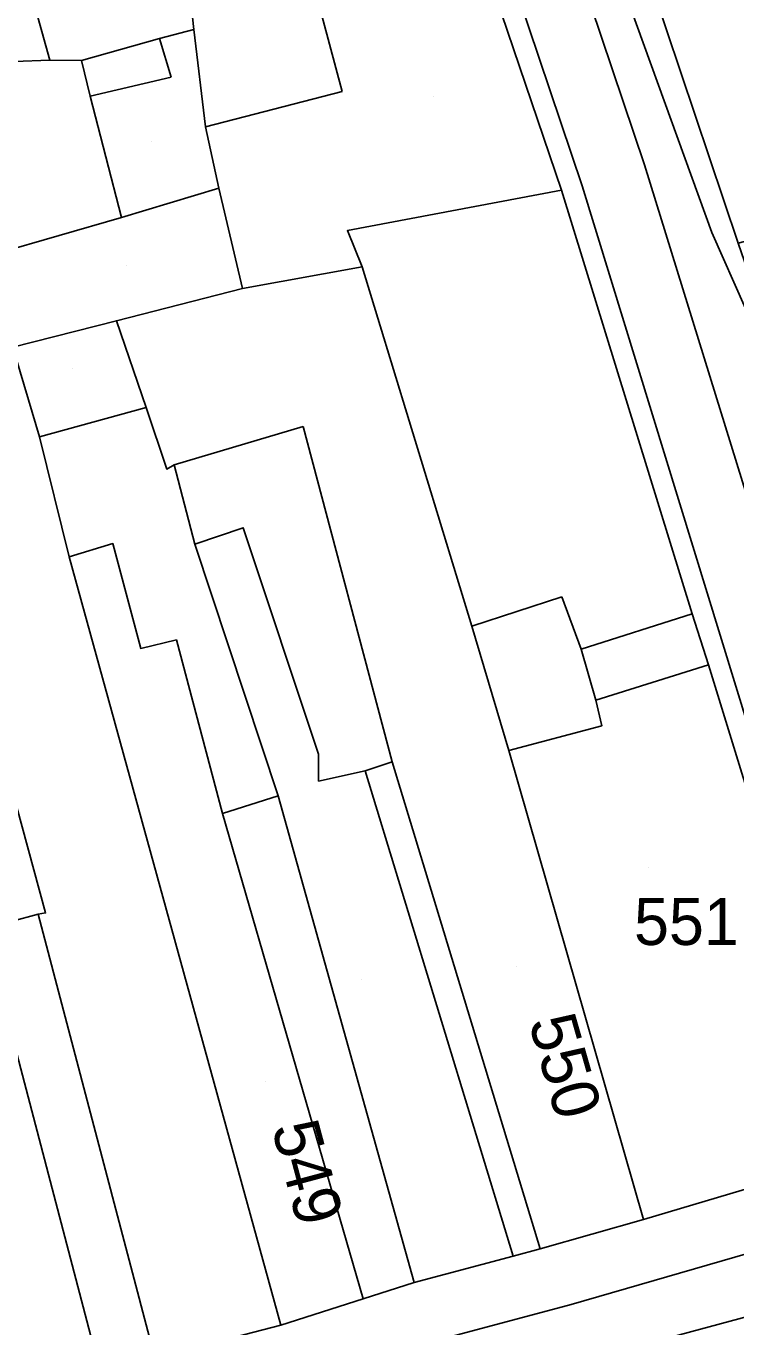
# Model space of a CAD drawing. Extents: x -263423 to -261326, y -1240067 to -1237864.
# Drawn here: x -262958.8 to -262928.5, y -1239629.8 to -1239574.4 of the extents above; entities that cross this region are included whole.
import ezdxf

# ---------------------------------------------------------------- set-up
doc = ezdxf.new("R2010")
doc.units = 0
for name, color, linetype in [('body_kn', 7, 'Continuous'), ('kladpar_druhypozemkov', 7, 'Continuous'), ('kladpar_hranice', 7, 'Continuous'), ('kladpar_parcelnecisla', 7, 'Continuous'), ('kladpar_plochy', 7, 'Continuous'), ('tarchy_linie', 7, 'Continuous'), ('zappar_hrandruhpozemk', 7, 'Continuous')]:
    doc.layers.add(name, color=color, linetype=linetype)

msp = doc.modelspace()

# ---------------------------------------------------------------- linework, layer by layer
at = {"layer": 'body_kn'}
for p, q in [((-262951.61, -1239574.56), (-262951.61, -1239574.56)), ((-262953.07, -1239574.94), (-262953.07, -1239574.94)), ((-262953.07, -1239574.94), (-262953.07, -1239574.94)), ((-262957.73, -1239575.87), (-262957.73, -1239575.87)), ((-262956.39, -1239575.88), (-262956.39, -1239575.88)), ((-262952.57, -1239576.6), (-262952.57, -1239576.6)), ((-262956.02, -1239577.41), (-262956.02, -1239577.41)), ((-262945.3, -1239577.21), (-262945.3, -1239577.21)), ((-262951.11, -1239578.71), (-262951.11, -1239578.71)), ((-262932.42, -1239580.33), (-262932.42, -1239580.33)), ((-262950.55, -1239581.32), (-262950.55, -1239581.32)), ((-262935.95, -1239581.4), (-262935.95, -1239581.4)), ((-262935.07, -1239581.22), (-262935.07, -1239581.22)), ((-262954.69, -1239582.57), (-262954.69, -1239582.57)), ((-262954.69, -1239582.57), (-262954.69, -1239582.57)), ((-262945.07, -1239583.13), (-262945.07, -1239583.13)), ((-262929.56, -1239583.21), (-262929.56, -1239583.21)), ((-262944.44, -1239584.67), (-262944.44, -1239584.67)), ((-262949.54, -1239585.6), (-262949.54, -1239585.6)), ((-262954.9, -1239586.97), (-262954.9, -1239586.97)), ((-262953.64, -1239590.67), (-262953.64, -1239590.67)), ((-262953.64, -1239590.67), (-262953.64, -1239590.67)), ((-262958.17, -1239591.92), (-262958.17, -1239591.92)), ((-262946.95, -1239591.47), (-262946.95, -1239591.47)), ((-262952.76, -1239593.29), (-262952.76, -1239593.29)), ((-262952.44, -1239593.1), (-262952.44, -1239593.1)), ((-262952.44, -1239593.1), (-262952.44, -1239593.1)), ((-262949.51, -1239595.79), (-262949.51, -1239595.79)), ((-262955.06, -1239596.46), (-262955.06, -1239596.46)), ((-262951.56, -1239596.48), (-262951.56, -1239596.48)), ((-262956.91, -1239597.03), (-262956.91, -1239597.03)), ((-262956.91, -1239597.03), (-262956.91, -1239597.03)), ((-262935.94, -1239598.73), (-262935.94, -1239598.73)), ((-262930.4, -1239599.46), (-262930.4, -1239599.46)), ((-262930.4, -1239599.46), (-262930.4, -1239599.46)), ((-262939.77, -1239599.98), (-262939.77, -1239599.98)), ((-262939.77, -1239599.98), (-262939.77, -1239599.98)), ((-262952.34, -1239600.56), (-262952.34, -1239600.56)), ((-262953.87, -1239600.93), (-262953.87, -1239600.93)), ((-262935.12, -1239600.96), (-262935.12, -1239600.96)), ((-262935.12, -1239600.96), (-262935.12, -1239600.96)), ((-262929.7, -1239601.63), (-262929.7, -1239601.63)), ((-262934.49, -1239603.13), (-262934.49, -1239603.13)), ((-262934.49, -1239603.13), (-262934.49, -1239603.13)), ((-262934.24, -1239604.22), (-262934.24, -1239604.22)), ((-262946.3, -1239605.43), (-262946.3, -1239605.43)), ((-262943.17, -1239605.76), (-262943.17, -1239605.76)), ((-262938.2, -1239605.28), (-262938.2, -1239605.28)), ((-262944.32, -1239606.14), (-262944.32, -1239606.14)), ((-262946.3, -1239606.58), (-262946.3, -1239606.58)), ((-262948.02, -1239607.2), (-262948.02, -1239607.2)), ((-262948.02, -1239607.2), (-262948.02, -1239607.2)), ((-262950.39, -1239607.96), (-262950.39, -1239607.96)), ((-262950.39, -1239607.96), (-262950.39, -1239607.96)), ((-262958.24, -1239612.25), (-262958.24, -1239612.25)), ((-262957.92, -1239612.19), (-262957.92, -1239612.19)), ((-262932.47, -1239625.25), (-262932.47, -1239625.25)), ((-262938.02, -1239626.82), (-262938.02, -1239626.82)), ((-262938.02, -1239626.82), (-262938.02, -1239626.82)), ((-262936.87, -1239626.5), (-262936.87, -1239626.5)), ((-262942.23, -1239627.94), (-262942.23, -1239627.94)), ((-262944.4, -1239628.63), (-262944.4, -1239628.63)), ((-262944.4, -1239628.63), (-262944.4, -1239628.63)), ((-262935.54, -1239628.87), (-262935.54, -1239628.87)), ((-262947.91, -1239629.76), (-262947.91, -1239629.76))]:
    msp.add_line(p, q, dxfattribs=at)
at = {"layer": 'kladpar_druhypozemkov'}
for p, q in [((-262941.39, -1239577.42), (-262941.39, -1239577.42)), ((-262953.39, -1239579.32), (-262953.39, -1239579.32)), ((-262954.49, -1239584.62), (-262954.49, -1239584.62)), ((-262956.79, -1239589.02), (-262956.79, -1239589.02)), ((-262932.27, -1239610.26), (-262932.27, -1239610.26)), ((-262937.87, -1239614.46), (-262937.87, -1239614.46)), ((-262944.49, -1239615.02), (-262944.49, -1239615.02)), ((-262948.57, -1239619.36), (-262948.57, -1239619.36))]:
    msp.add_line(p, q, dxfattribs=at)
at = {"layer": 'kladpar_hranice'}
for points in [[(-262869.06, -1239540.52), (-262844.5, -1239533.52), (-262841.03, -1239544.11), (-262840.53, -1239545.7), (-262836.49, -1239558.34), (-262849.7, -1239561.9), (-262861.12, -1239565.66), (-262879.23, -1239570.41), (-262884.4, -1239571.98), (-262891.48, -1239573.92), (-262893.14, -1239574.42), (-262895.06, -1239574.86), (-262928.43, -1239583.67), (-262932.09, -1239572.75), (-262933.04, -1239569.94), (-262936.63, -1239559.6), (-262926.55, -1239556.66), (-262923.3, -1239555.79), (-262917.99, -1239554.32), (-262895.92, -1239548.22), (-262869.06, -1239540.52)], [(-262946.11, -1239551.91), (-262940.62, -1239567.74), (-262939.79, -1239570.1), (-262935.95, -1239581.4), (-262945.07, -1239583.13), (-262944.44, -1239584.67), (-262949.54, -1239585.6), (-262950.55, -1239581.32), (-262951.11, -1239578.71), (-262951.61, -1239574.56), (-262951.79, -1239572.84), (-262952.3, -1239571.25), (-262956.89, -1239555.04), (-262946.11, -1239551.91)], [(-262952.3, -1239571.25), (-262951.79, -1239572.84), (-262951.61, -1239574.56), (-262951.11, -1239578.71), (-262950.55, -1239581.32), (-262949.54, -1239585.6), (-262954.9, -1239586.97), (-262959.31, -1239588.09), (-262960.31, -1239584.2), (-262960.63, -1239583.05), (-262961.07, -1239583.05), (-262963.03, -1239576.54), (-262963.78, -1239574.05), (-262967.94, -1239558.17), (-262964.55, -1239557.16), (-262963.09, -1239556.79), (-262956.89, -1239555.04), (-262952.3, -1239571.25)], [(-262932.09, -1239572.75), (-262928.43, -1239583.67), (-262926.6, -1239588.96), (-262925.59, -1239592.22), (-262923.77, -1239600.07), (-262922.26, -1239606.32), (-262921.38, -1239609.7), (-262926.74, -1239611.26), (-262929.7, -1239601.63), (-262930.4, -1239599.46), (-262935.95, -1239581.4), (-262939.79, -1239570.1)], [(-262930.4, -1239599.46), (-262929.7, -1239601.63), (-262926.74, -1239611.26), (-262923.4, -1239622.56), (-262932.47, -1239625.25), (-262938.2, -1239605.28), (-262939.77, -1239599.98), (-262944.44, -1239584.67), (-262945.07, -1239583.13), (-262935.95, -1239581.4), (-262930.4, -1239599.46)], [(-262939.77, -1239599.98), (-262938.2, -1239605.28), (-262932.47, -1239625.25), (-262936.87, -1239626.5), (-262938.02, -1239626.82), (-262942.23, -1239627.94), (-262948.02, -1239607.2), (-262951.56, -1239596.48), (-262952.44, -1239593.1), (-262952.76, -1239593.29), (-262953.64, -1239590.67), (-262954.9, -1239586.97), (-262949.54, -1239585.6), (-262944.44, -1239584.67), (-262939.77, -1239599.98)], [(-262948.02, -1239607.2), (-262942.23, -1239627.94), (-262944.4, -1239628.63), (-262947.91, -1239629.76), (-262956.91, -1239597.03), (-262958.17, -1239591.92), (-262959.31, -1239588.09), (-262954.9, -1239586.97), (-262953.64, -1239590.67), (-262952.76, -1239593.29), (-262952.44, -1239593.1), (-262951.56, -1239596.48), (-262948.02, -1239607.2)], [(-262959.31, -1239588.09), (-262958.17, -1239591.92), (-262956.91, -1239597.03), (-262947.91, -1239629.76), (-262953.27, -1239631.14), (-262955.64, -1239631.57), (-262964.44, -1239633.88), (-262975.97, -1239593.61), (-262976.09, -1239593.1), (-262971.11, -1239591.16), (-262959.31, -1239588.09)], [(-262996.87, -1239642.57), (-262991.31, -1239641.17), (-262990.43, -1239640.95), (-262989.01, -1239640.57), (-262986.91, -1239640.01), (-262985.7, -1239639.7), (-262980.21, -1239638.2), (-262975.17, -1239636.82), (-262971.98, -1239635.95), (-262969.42, -1239635.32), (-262964.44, -1239633.88), (-262955.64, -1239631.57), (-262953.27, -1239631.14), (-262947.91, -1239629.76), (-262944.4, -1239628.63), (-262942.23, -1239627.94), (-262938.02, -1239626.82), (-262936.87, -1239626.5), (-262932.47, -1239625.25), (-262923.4, -1239622.56)]]:
    msp.add_lwpolyline(points, dxfattribs=at)
at = {"layer": 'kladpar_plochy'}
for points in [[(-262869.06, -1239540.52), (-262844.5, -1239533.52), (-262841.03, -1239544.11), (-262840.53, -1239545.7), (-262836.49, -1239558.34), (-262849.7, -1239561.9), (-262861.12, -1239565.66), (-262879.23, -1239570.41), (-262884.4, -1239571.98), (-262891.48, -1239573.92), (-262893.14, -1239574.42), (-262895.06, -1239574.86), (-262928.43, -1239583.67), (-262932.09, -1239572.75), (-262933.04, -1239569.94), (-262936.63, -1239559.6), (-262926.55, -1239556.66), (-262923.3, -1239555.79), (-262917.99, -1239554.32), (-262895.92, -1239548.22)], [(-262946.11, -1239551.91), (-262940.62, -1239567.74), (-262939.79, -1239570.1), (-262935.95, -1239581.4), (-262945.07, -1239583.13), (-262944.44, -1239584.67), (-262949.54, -1239585.6), (-262950.55, -1239581.32), (-262951.11, -1239578.71), (-262951.61, -1239574.56), (-262951.79, -1239572.84), (-262952.3, -1239571.25), (-262956.89, -1239555.04)], [(-262952.3, -1239571.25), (-262951.79, -1239572.84), (-262951.61, -1239574.56), (-262951.11, -1239578.71), (-262950.55, -1239581.32), (-262949.54, -1239585.6), (-262954.9, -1239586.97), (-262959.31, -1239588.09), (-262960.31, -1239584.2), (-262960.63, -1239583.05), (-262961.07, -1239583.05), (-262963.03, -1239576.54), (-262963.78, -1239574.05), (-262967.94, -1239558.17), (-262964.55, -1239557.16), (-262963.09, -1239556.79), (-262956.89, -1239555.04)], [(-262930.4, -1239599.46), (-262929.7, -1239601.63), (-262926.74, -1239611.26), (-262923.4, -1239622.56), (-262932.47, -1239625.25), (-262938.2, -1239605.28), (-262939.77, -1239599.98), (-262944.44, -1239584.67), (-262945.07, -1239583.13), (-262935.95, -1239581.4)], [(-262939.77, -1239599.98), (-262938.2, -1239605.28), (-262932.47, -1239625.25), (-262936.87, -1239626.5), (-262938.02, -1239626.82), (-262942.23, -1239627.94), (-262948.02, -1239607.2), (-262951.56, -1239596.48), (-262952.44, -1239593.1), (-262952.76, -1239593.29), (-262953.64, -1239590.67), (-262954.9, -1239586.97), (-262949.54, -1239585.6), (-262944.44, -1239584.67)], [(-262948.02, -1239607.2), (-262942.23, -1239627.94), (-262944.4, -1239628.63), (-262947.91, -1239629.76), (-262956.91, -1239597.03), (-262958.17, -1239591.92), (-262959.31, -1239588.09), (-262954.9, -1239586.97), (-262953.64, -1239590.67), (-262952.76, -1239593.29), (-262952.44, -1239593.1), (-262951.56, -1239596.48)], [(-262959.31, -1239588.09), (-262958.17, -1239591.92), (-262956.91, -1239597.03), (-262947.91, -1239629.76), (-262953.27, -1239631.14), (-262955.64, -1239631.57), (-262964.44, -1239633.88), (-262975.97, -1239593.61), (-262976.09, -1239593.1), (-262971.11, -1239591.16)]]:
    msp.add_lwpolyline(points, close=True, dxfattribs=at)
for points in [[(-262932.09, -1239572.75), (-262928.43, -1239583.67), (-262926.6, -1239588.96), (-262925.59, -1239592.22), (-262923.77, -1239600.07), (-262922.26, -1239606.32), (-262921.38, -1239609.7), (-262926.74, -1239611.26), (-262929.7, -1239601.63), (-262930.4, -1239599.46), (-262935.95, -1239581.4), (-262939.79, -1239570.1)], [(-262989.01, -1239640.57), (-262986.91, -1239640.01), (-262985.7, -1239639.7), (-262980.21, -1239638.2), (-262975.17, -1239636.82), (-262971.98, -1239635.95), (-262969.42, -1239635.32), (-262964.44, -1239633.88), (-262955.64, -1239631.57), (-262953.27, -1239631.14), (-262947.91, -1239629.76), (-262944.4, -1239628.63), (-262942.23, -1239627.94), (-262938.02, -1239626.82), (-262936.87, -1239626.5), (-262932.47, -1239625.25), (-262923.4, -1239622.56)]]:
    msp.add_lwpolyline(points, dxfattribs=at)
at = {"layer": 'tarchy_linie'}
for points in [[(-262952.77, -1239538.58), (-262950.32, -1239537.86), (-262948.45, -1239537.31), (-262945.97, -1239537.82), (-262929.56, -1239583.21), (-262926.69, -1239589.69), (-262925.17, -1239595.04), (-262922.55, -1239607.14), (-262922.37, -1239609.59), (-262916.97, -1239626.37)], [(-262944.3, -1239545.03), (-262932.42, -1239580.33), (-262923.42, -1239609.49), (-262918.19, -1239626.73)], [(-262915.48, -1239625.94), (-262916.97, -1239626.37), (-262918.19, -1239626.73), (-262920.89, -1239627.46), (-262935.07, -1239581.22), (-262946.48, -1239547.32)], [(-262932.09, -1239572.75), (-262928.43, -1239583.67), (-262926.6, -1239588.96), (-262925.59, -1239592.22), (-262923.77, -1239600.07), (-262922.26, -1239606.32), (-262921.38, -1239609.7), (-262918.36, -1239621.25), (-262917.53, -1239620.93), (-262917.06, -1239620.79), (-262915.89, -1239624.66), (-262915.48, -1239625.94)], [(-263078.58, -1239671.12), (-263027.36, -1239656.4), (-262972.56, -1239641.44), (-262972.57, -1239641.39), (-262918.15, -1239626.72), (-262867.77, -1239611.96), (-262836.79, -1239602.77), (-262835.73, -1239601.81), (-262832.52, -1239600.46), (-262815.98, -1239594.96), (-262815.48, -1239596.45), (-262814.98, -1239597.94), (-262817.32, -1239598.72), (-262817.29, -1239598.81), (-262816.79, -1239600.49), (-262835.82, -1239606.13), (-262840.12, -1239610.01), (-262915.13, -1239632.71), (-262924.39, -1239633.58), (-262985.09, -1239649.35), (-263038.78, -1239664.15)]]:
    msp.add_lwpolyline(points, dxfattribs=at)
at = {"layer": 'zappar_hrandruhpozemk'}
for p, q in [((-262963.09, -1239556.79), (-262957.73, -1239575.87)), ((-262946.62, -1239572.23), (-262945.3, -1239577.21)), ((-262953.07, -1239574.94), (-262951.61, -1239574.56)), ((-262956.39, -1239575.88), (-262953.07, -1239574.94)), ((-262952.57, -1239576.6), (-262953.07, -1239574.94)), ((-262956.39, -1239575.88), (-262956.02, -1239577.41)), ((-262956.02, -1239577.41), (-262952.57, -1239576.6)), ((-262956.02, -1239577.41), (-262954.69, -1239582.57)), ((-262945.3, -1239577.21), (-262951.11, -1239578.71)), ((-262954.69, -1239582.57), (-262950.55, -1239581.32)), ((-262960.31, -1239584.2), (-262954.69, -1239582.57)), ((-262953.64, -1239590.67), (-262958.17, -1239591.92)), ((-262952.44, -1239593.1), (-262946.95, -1239591.47)), ((-262946.95, -1239591.47), (-262943.17, -1239605.76)), ((-262939.77, -1239599.98), (-262935.94, -1239598.73)), ((-262935.12, -1239600.96), (-262930.4, -1239599.46)), ((-262952.34, -1239600.56), (-262950.39, -1239607.96)), ((-262934.49, -1239603.13), (-262929.7, -1239601.63)), ((-262943.17, -1239605.76), (-262936.87, -1239626.5)), ((-262938.02, -1239626.82), (-262944.32, -1239606.14)), ((-262950.39, -1239607.96), (-262948.02, -1239607.2)), ((-262944.4, -1239628.63), (-262950.39, -1239607.96)), ((-262953.27, -1239631.14), (-262958.24, -1239612.25)), ((-262960.54, -1239612.87), (-262955.64, -1239631.57))]:
    msp.add_line(p, q, dxfattribs=at)
for points in [[(-262963.03, -1239576.54), (-262960.92, -1239575.98), (-262959.26, -1239575.92), (-262957.73, -1239575.87), (-262956.39, -1239575.88)], [(-262970.62, -1239596), (-262962.9, -1239593.87), (-262957.92, -1239612.19), (-262958.24, -1239612.25), (-262960.54, -1239612.87), (-262965.33, -1239614.06)], [(-262943.17, -1239605.76), (-262944.32, -1239606.14), (-262946.3, -1239606.58), (-262946.3, -1239605.43), (-262949.51, -1239595.79), (-262951.56, -1239596.48)], [(-262956.91, -1239597.03), (-262955.06, -1239596.46), (-262953.87, -1239600.93), (-262952.34, -1239600.56)], [(-262935.94, -1239598.73), (-262935.12, -1239600.96), (-262934.49, -1239603.13), (-262934.24, -1239604.22), (-262938.2, -1239605.28)], [(-262989.48, -1239643.76), (-262957.56, -1239634.75), (-262935.54, -1239628.87), (-262924.5, -1239625.68), (-262923.86, -1239624.85), (-262923.54, -1239624.02), (-262923.41, -1239623.32), (-262923.4, -1239622.56)]]:
    msp.add_lwpolyline(points, dxfattribs=at)

# ---------------------------------------------------------------- texts
at = {"layer": 'kladpar_parcelnecisla'}
msp.add_text('551', height=2, dxfattribs=at).set_placement((-262932.87, -1239613.56))
for s, rotation, p in [('550', 286, (-262937.364, -1239616.829)), ('549', 285, (-262948.305, -1239621.335))]:
    msp.add_text(s, height=2, rotation=rotation, dxfattribs=at).set_placement(p)

doc.saveas('drawing.dxf')
